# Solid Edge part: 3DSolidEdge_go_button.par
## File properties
Author: Administrator
Last saved by: Administrator
Revision: 49
Accuracy: 0.990
Agile_Description: Go Button Part
Modeled_By: L. Conard
Part_Number: ITEM-SE-00006
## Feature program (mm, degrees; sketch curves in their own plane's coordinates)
body "unnamed Body 1"
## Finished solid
Body 1: solid body, 15 faces, 33 edges, 20 vertices.
  Faces by surface: plane 13, cylinder 1, torus 1
  Edges by curve: line 30, circle 3
Bounding box of the edges (mm; curved faces can reach further): 10.000 x 10.000 x 3.200, from (-5, -5, 0) to (5, 5, 3.2).
Cylindrical faces by radius (mm): R5 x1
Toroidal faces (ring radius, tube radius in mm): R4 r1 x1
Planar faces by outward normal: +y 2, +z 2, -z 1, oblique 8
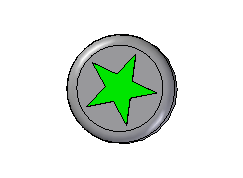
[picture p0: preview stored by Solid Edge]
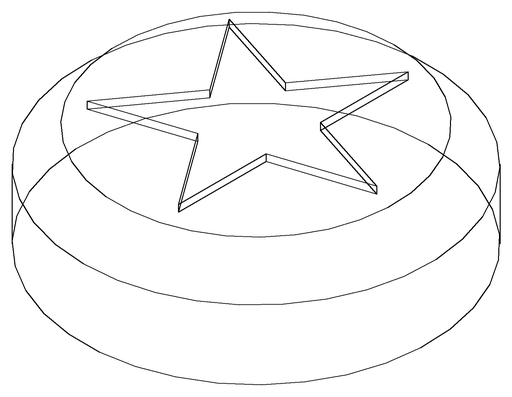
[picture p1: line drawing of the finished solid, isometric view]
